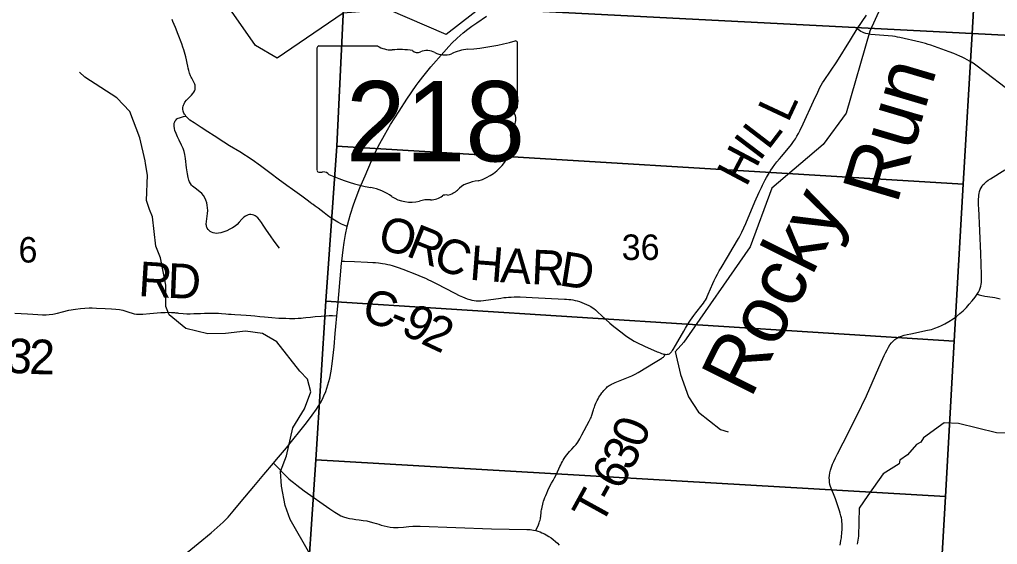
# Model space of a CAD drawing. Extents: x 0 to 34, y 0 to 22.
# Drawn here: x 26.889 to 28.495, y 15.04 to 15.902 of the extents above; entities that cross this region are included whole.
import ezdxf

# ---------------------------------------------------------------- set-up
doc = ezdxf.new("R2010")
doc.units = 0
for name, color, linetype in [('GM_X_County_Road', 7, 'Continuous'), ('GM_X_County_Road_Text', 7, 'Continuous'), ('GM_X_Minor_River', 7, 'Continuous'), ('GM_X_Minor_River_Text', 7, 'Continuous'), ('GM_X_Section', 7, 'Continuous'), ('GM_X_Section_Text', 7, 'Continuous'), ('GM_X_State_Location', 7, 'Continuous'), ('GM_X_State_Route', 7, 'Continuous'), ('GM_X_State_Shield', 7, 'Continuous'), ('GM_X_Township_Road', 7, 'Continuous'), ('GM_X_Township_Road_Text', 7, 'Continuous')]:
    doc.layers.add(name, color=color, linetype=linetype)

msp = doc.modelspace()

# ---------------------------------------------------------------- linework, layer by layer
at = {"layer": 'GM_X_County_Road'}
for points in [[(27.376, 15.5941), (27.3744, 15.5953), (27.3711, 15.5978), (27.3692, 15.5992), (27.3663, 15.6014), (27.3614, 15.6052), (27.3526, 15.6117), (27.3449, 15.6173), (27.3374, 15.6228), (27.3281, 15.6294), (27.3139, 15.6396), (27.3022, 15.6483), (27.2846, 15.6614), (27.2709, 15.6714), (27.2506, 15.6845), (27.2339, 15.6941), (27.2244, 15.7003), (27.2084, 15.7105), (27.1981, 15.7174), (27.187, 15.7245), (27.1757, 15.732), (27.1688, 15.7366), (27.1645, 15.7403), (27.1631, 15.7418), (27.1619, 15.7431), (27.1607, 15.7449), (27.1597, 15.7464), (27.1589, 15.748), (27.1576, 15.7514), (27.1571, 15.7543), (27.1572, 15.7573), (27.1576, 15.7595), (27.1581, 15.7611), (27.159, 15.7632), (27.1605, 15.7658), (27.1632, 15.7691), (27.1649, 15.7708), (27.1713, 15.7773), (27.1735, 15.78), (27.1753, 15.7826), (27.1766, 15.7849), (27.1769, 15.7857), (27.1771, 15.7867), (27.1775, 15.7884), (27.1775, 15.7912), (27.1772, 15.7937), (27.1767, 15.7953), (27.1756, 15.7977), (27.1735, 15.8021), (27.1718, 15.8055), (27.171, 15.8071), (27.1698, 15.8093), (27.168, 15.8138), (27.1675, 15.8155), (27.1669, 15.8179), (27.166, 15.8215), (27.1652, 15.825), (27.1642, 15.8298), (27.1633, 15.8353), (27.162, 15.8405), (27.1588, 15.8517), (27.1572, 15.8564), (27.1554, 15.8615), (27.1496, 15.8772), (27.1449, 15.8887), (27.1408, 15.8984), (27.1393, 15.9015)], [(28.2648, 15.8862), (28.2802, 15.9088)], [(27.4183, 15.505), (27.4226, 15.5049), (27.439, 15.5044), (27.4603, 15.5035), (27.469, 15.503), (27.4738, 15.5027), (27.4785, 15.5021), (27.4818, 15.5017), (27.4853, 15.5012), (27.4894, 15.5005), (27.4938, 15.4997), (27.4973, 15.4988), (27.5011, 15.4978), (27.5056, 15.4963), (27.511, 15.4945), (27.5185, 15.4918), (27.5406, 15.4832), (27.5488, 15.4798), (27.5554, 15.4769), (27.5605, 15.4745), (27.5646, 15.4725), (27.5689, 15.4704), (27.5731, 15.4683), (27.6038, 15.4524), (27.611, 15.4486), (27.6164, 15.4462), (27.6205, 15.4445), (27.6242, 15.4432), (27.6287, 15.4419), (27.632, 15.441), (27.6355, 15.4404), (27.639, 15.44), (27.6429, 15.4398), (27.6468, 15.44), (27.6511, 15.4403), (27.6793, 15.4444), (27.6843, 15.4451), (27.6881, 15.4455), (27.6919, 15.4459), (27.6965, 15.4461), (27.7012, 15.4463), (27.706, 15.4463), (27.7113, 15.4463), (27.7308, 15.4455), (27.7838, 15.4426), (27.7875, 15.4425), (27.7909, 15.4422), (27.7943, 15.4419), (27.7978, 15.4413), (27.8013, 15.4406), (27.8048, 15.4398), (27.8085, 15.4386), (27.8125, 15.4372), (27.8162, 15.4357), (27.8202, 15.434), (27.8237, 15.4324), (27.827, 15.4306), (27.8295, 15.429), (27.8321, 15.4271), (27.835, 15.4249), (27.8381, 15.422), (27.8451, 15.4152), (27.8584, 15.4034), (27.8651, 15.3977), (27.8785, 15.3872), (27.882, 15.3847), (27.8865, 15.3814), (27.8986, 15.3738), (27.9026, 15.3717), (27.9074, 15.3693), (27.9112, 15.3674), (27.9151, 15.3656), (27.9362, 15.3564), (27.9386, 15.3554), (27.941, 15.3544), (27.9433, 15.3536), (27.9456, 15.3529), (27.9467, 15.3525), (27.9476, 15.3523), (27.9485, 15.3522), (27.9495, 15.3521), (27.9514, 15.352), (27.9533, 15.3521), (27.9548, 15.3525), (27.9564, 15.353), (27.9576, 15.3539), (27.9586, 15.3548), (27.9596, 15.3559), (27.9605, 15.3571), (27.9615, 15.3584), (27.9625, 15.36), (27.9701, 15.3732), (27.9797, 15.39), (27.9827, 15.395), (27.9858, 15.4002), (27.9887, 15.4046), (27.9911, 15.408), (27.9937, 15.4117), (27.9965, 15.4156), (27.9997, 15.4199), (28.0101, 15.4331), (28.0123, 15.4361), (28.014, 15.4385), (28.0155, 15.441), (28.0171, 15.4439), (28.0185, 15.4469), (28.0202, 15.4506), (28.0278, 15.4682), (28.03, 15.4731), (28.0327, 15.4786), (28.0352, 15.4834), (28.0382, 15.4891), (28.0411, 15.494), (28.0516, 15.5116), (28.0611, 15.5272), (28.0698, 15.5422), (28.0717, 15.5458), (28.0736, 15.5495), (28.075, 15.5524), (28.0816, 15.567), (28.0967, 15.6023), (28.1038, 15.618), (28.1073, 15.6256), (28.1093, 15.6299), (28.1115, 15.6342), (28.1136, 15.6382), (28.116, 15.6424), (28.1207, 15.6503), (28.123, 15.6541), (28.1255, 15.6581), (28.1293, 15.6635), (28.1327, 15.6678), (28.137, 15.673), (28.1409, 15.6774), (28.1566, 15.6963), (28.1603, 15.7011), (28.1633, 15.7056), (28.1658, 15.7099), (28.1682, 15.7143), (28.1711, 15.7201), (28.1762, 15.7305), (28.193, 15.7674), (28.2, 15.7826), (28.2018, 15.7864), (28.2036, 15.7898), (28.2057, 15.7937), (28.2078, 15.7974), (28.2105, 15.8016), (28.2311, 15.8321), (28.2537, 15.8685), (28.2648, 15.8862)], [(28.5076, 15.7901), (28.4779, 15.8128), (28.4573, 15.8282), (28.4534, 15.8308), (28.4491, 15.8335), (28.4453, 15.8356), (28.4417, 15.8374), (28.4372, 15.8397), (28.4332, 15.8416), (28.4283, 15.8438), (28.4234, 15.8459), (28.4156, 15.8488), (28.3858, 15.8593), (28.3815, 15.8608), (28.3771, 15.8621), (28.3726, 15.8634), (28.3682, 15.8645), (28.3346, 15.8722), (28.3309, 15.8728), (28.3269, 15.8735), (28.3227, 15.874), (28.2869, 15.8772), (28.2823, 15.8779), (28.2789, 15.8786), (28.2757, 15.8796), (28.2732, 15.8807), (28.2709, 15.8819), (28.2684, 15.8834), (28.2648, 15.8862)], [(28.3323, 15.38), (28.3331, 15.3805), (28.3372, 15.3821), (28.3416, 15.3834), (28.3468, 15.3846), (28.3527, 15.3859), (28.3804, 15.3915), (28.3865, 15.393), (28.3923, 15.3948), (28.398, 15.3969), (28.4032, 15.3993), (28.4089, 15.4022), (28.4152, 15.4059), (28.4226, 15.4104), (28.4279, 15.4143), (28.4334, 15.4188), (28.4386, 15.4234), (28.4442, 15.4291), (28.4488, 15.4342), (28.4536, 15.4397), (28.4582, 15.4457), (28.4618, 15.451), (28.4637, 15.454), (28.4654, 15.4573), (28.4668, 15.4608), (28.4678, 15.464), (28.4684, 15.4671), (28.4688, 15.47), (28.4691, 15.4734), (28.4691, 15.4768), (28.469, 15.4823), (28.4676, 15.5174), (28.4643, 15.5922), (28.4641, 15.5961), (28.464, 15.6003), (28.464, 15.6035), (28.4641, 15.6066), (28.4643, 15.6104), (28.4645, 15.6132), (28.465, 15.6162), (28.4658, 15.6193), (28.4668, 15.6224), (28.4683, 15.6255), (28.4697, 15.6278), (28.4713, 15.63), (28.473, 15.6318), (28.4747, 15.6335), (28.4771, 15.6356), (28.48, 15.6378), (28.4834, 15.64), (28.5073, 15.6547)], [(27.427, 15.5618), (27.423, 15.5633), (27.4178, 15.5656), (27.4119, 15.5687), (27.4009, 15.5757), (27.3948, 15.5799), (27.3892, 15.5842), (27.3842, 15.5881), (27.3792, 15.5918), (27.376, 15.5941)], [(28.2365, 15.039), (28.2373, 15.0427), (28.238, 15.0467), (28.2387, 15.0508), (28.2391, 15.0544), (28.2395, 15.0574), (28.2397, 15.0608), (28.2399, 15.0637), (28.2399, 15.0742), (28.2397, 15.0773), (28.2393, 15.0806), (28.2389, 15.0834), (28.2381, 15.0867), (28.237, 15.0911), (28.2359, 15.0949), (28.2289, 15.1148), (28.221, 15.135), (28.22, 15.1386), (28.2194, 15.142), (28.219, 15.1455), (28.2188, 15.1491), (28.2191, 15.1531), (28.2198, 15.1574), (28.2208, 15.1619), (28.2225, 15.167), (28.2244, 15.1716), (28.2263, 15.1762), (28.2291, 15.182), (28.2323, 15.1887), (28.2415, 15.2069), (28.2643, 15.2511), (28.28, 15.2838), (28.3043, 15.3393), (28.3069, 15.345), (28.3092, 15.3499), (28.3113, 15.3545), (28.3138, 15.3595), (28.3161, 15.3637), (28.3185, 15.3676), (28.321, 15.3707), (28.3239, 15.3739), (28.3267, 15.3765), (28.3298, 15.3787), (28.3323, 15.38)], [(27.306, 15.1733), (27.3081, 15.1711), (27.3256, 15.1532), (27.3292, 15.1498), (27.3314, 15.1478), (27.3347, 15.1451), (27.339, 15.1416), (27.3445, 15.1372), (27.3566, 15.1281), (27.3986, 15.0982), (27.4069, 15.0928), (27.4121, 15.0896), (27.4166, 15.0871), (27.4211, 15.0853), (27.4262, 15.0837), (27.4311, 15.0825), (27.4357, 15.0818), (27.441, 15.081), (27.4468, 15.0804), (27.4533, 15.0795), (27.4591, 15.0785), (27.4648, 15.0773), (27.4709, 15.0757), (27.4751, 15.0744), (27.4789, 15.0731), (27.4829, 15.0719), (27.4878, 15.0705), (27.4928, 15.0692), (27.4978, 15.0684), (27.5032, 15.0678), (27.5109, 15.0678), (27.5195, 15.0684), (27.5281, 15.0692), (27.5349, 15.0698), (27.5407, 15.0699), (27.5467, 15.0698), (27.664, 15.0656), (27.7223, 15.0645), (27.7274, 15.0643), (27.7305, 15.064), (27.7332, 15.0635), (27.737, 15.0627), (27.7403, 15.0617), (27.7438, 15.0606), (27.7469, 15.0592), (27.7509, 15.0573), (27.7541, 15.0555), (27.7582, 15.0532), (27.7618, 15.0508), (27.7656, 15.0479), (27.7692, 15.0451), (27.7725, 15.042), (27.7754, 15.0386)]]:
    msp.add_lwpolyline(points, dxfattribs=at)
at = {"layer": 'GM_X_Minor_River'}
for points in [[(28.4678, 16.383), (28.4473, 16.2989), (28.4687, 16.2373), (28.4626, 16.2034), (28.4068, 16.1494), (28.3695, 16.0675), (28.2854, 15.8822), (28.2465, 15.7479), (28.2089, 15.6967), (28.1244, 15.6246), (28.0888, 15.5286), (27.98, 15.372), (27.9658, 15.356)], [(27.8486, 15.9861), (27.7758, 15.951), (27.6723, 15.9417), (27.5896, 15.8768), (27.4942, 15.9181), (27.4206, 15.9121), (27.3119, 15.8379), (27.2763, 15.8588), (27.2368, 15.9154)], [(27.3116, 15.3727), (27.2881, 15.386), (27.26, 15.3902), (27.2271, 15.3863), (27.1982, 15.3856), (27.1619, 15.3946), (27.1349, 15.4171), (27.1289, 15.4304), (27.1289, 15.4657), (27.1202, 15.5106), (27.1126, 15.5296), (27.107, 15.5779), (27.1024, 15.5896), (27.0975, 15.6045), (27.099, 15.6463), (27.0956, 15.6653), (27.0952, 15.6695), (27.0862, 15.7075), (27.0702, 15.7508), (27.0486, 15.7732), (26.9963, 15.807), (26.9873, 15.8154)], [(27.4801, 14.9479), (27.4347, 15.0056), (27.406, 15.0186), (27.3843, 15.0231), (27.3658, 15.0245), (27.3335, 15.081), (27.3251, 15.104), (27.3189, 15.1354), (27.3177, 15.1597), (27.3275, 15.1852), (27.338, 15.2316), (27.3571, 15.2625), (27.3674, 15.2906), (27.3616, 15.3113), (27.3495, 15.3246), (27.3115, 15.3728)], [(27.9655, 15.3569), (27.9744, 15.3187), (27.9874, 15.2821), (28.004, 15.2569), (28.0402, 15.2289), (28.0527, 15.225)], [(28.5405, 15.2213), (28.4933, 15.2231), (28.431, 15.2384), (28.4076, 15.2396), (28.3736, 15.2148), (28.3693, 15.2081), (28.3619, 15.2038), (28.3474, 15.1872), (28.3347, 15.1785), (28.3334, 15.1724), (28.3072, 15.1558), (28.2823, 15.1201), (28.2677, 15.0993), (28.267, 15.0538), (28.2644, 15.0406)]]:
    msp.add_lwpolyline(points, dxfattribs=at)
at = {"layer": 'GM_X_Section'}
for points in [[(27.7176, 16.0274), (28.4594, 15.9845), (28.4533, 15.8787), (27.7054, 15.9168)], [(26.3734, 15.9843), (27.4216, 15.9328), (27.4099, 15.6936), (27.392, 15.4391), (27.3753, 15.1787), (27.3574, 14.9107), (27.3572, 14.9074), (26.2944, 14.9601)], [(28.4594, 15.9845), (29.1085, 15.9479), (29.1198, 15.9322), (29.1285, 15.9182), (29.151, 15.885), (29.1594, 15.8732), (29.1693, 15.86), (29.1769, 15.8494), (29.1887, 15.8408), (28.6965, 15.8662), (28.4533, 15.8787)], [(27.4216, 15.9328), (27.7054, 15.9168), (28.4533, 15.8787), (28.439, 15.6312), (27.4099, 15.6936)], [(28.4533, 15.8787), (28.6965, 15.8662), (28.6747, 15.5464), (28.6572, 15.29), (28.6412, 15.0549), (28.6267, 14.8415), (28.3943, 14.8549), (28.4095, 15.1186), (28.4242, 15.3738), (28.439, 15.6312)], [(28.439, 15.6312), (28.4242, 15.3738), (27.392, 15.4391), (27.4099, 15.6936)], [(27.392, 15.4391), (28.4242, 15.3738), (28.4095, 15.1186), (27.3753, 15.1787)], [(28.4095, 15.1186), (28.3943, 14.8549), (27.3574, 14.9107), (27.3753, 15.1787)]]:
    msp.add_lwpolyline(points, close=True, dxfattribs=at)
at = {"layer": 'GM_X_State_Route'}
msp.add_lwpolyline([(27.1584, 15.0216), (27.1824, 15.0415), (27.2035, 15.0591), (27.2234, 15.0768), (27.2313, 15.085), (27.2398, 15.0947), (27.2531, 15.1105), (27.2739, 15.1353), (27.2902, 15.1548), (27.306, 15.1733), (27.3111, 15.1794), (27.3274, 15.1988), (27.3379, 15.2118), (27.3495, 15.2261), (27.36, 15.2394), (27.3696, 15.2521), (27.3766, 15.2621), (27.3834, 15.2726), (27.3864, 15.2785), (27.3886, 15.2837), (27.3917, 15.2913), (27.3954, 15.3021), (27.3985, 15.3128), (27.4008, 15.3245), (27.4025, 15.3365), (27.4054, 15.3641), (27.4073, 15.386), (27.4084, 15.3975), (27.4099, 15.4155), (27.4114, 15.4312), (27.4131, 15.4503), (27.4155, 15.4758), (27.4179, 15.5015), (27.4183, 15.505), (27.4203, 15.5235), (27.422, 15.5358), (27.4242, 15.5489), (27.427, 15.5618), (27.4296, 15.5722), (27.4323, 15.5822), (27.4373, 15.5975), (27.4416, 15.6095), (27.448, 15.6254), (27.4563, 15.645), (27.4671, 15.6699), (27.4736, 15.6844), (27.4804, 15.6981), (27.4881, 15.7119), (27.4981, 15.7291), (27.5126, 15.7514), (27.525, 15.7706), (27.5403, 15.7932), (27.5436, 15.7978), (27.5512, 15.8077), (27.5646, 15.8237), (27.5855, 15.8479), (27.594, 15.8573), (27.5991, 15.8627), (27.6075, 15.8708), (27.6177, 15.8796), (27.6252, 15.8857), (27.6316, 15.8906), (27.64, 15.8964), (27.6558, 15.9073)], dxfattribs=at)
at = {"layer": 'GM_X_State_Shield'}
for p, q in [((27.3774, 15.8547), (27.3774, 15.6546)), ((27.4772, 15.8581), (27.3807, 15.8581)), ((27.707, 15.7584), (27.707, 15.8631)), ((27.707, 15.7584), (27.707, 15.7584))]:
    msp.add_line(p, q, dxfattribs=at)
for centre, major_axis, start_param, end_param in [((27.3812, 15.8551), (0.00382, 0), 1.712693, 3.28349), ((27.5002, 15.8813), (0.037, 0), 4.042523, 4.731795), ((27.6342, 15.797), (0.0703, 0), 1.699011, 2.107814), ((27.5896, 16.1309), (0.3495, 0), 4.814394, 5.042369), ((27.7033, 15.8635), (0.00367, 0), 6.141152, 7.989035), ((27.5124, 15.7458), (0.133, 0), 1.404758, 1.657858), ((27.5426, 15.8561), (0.0107, 0), 3.836095, 5.185415), ((27.5583, 15.833), (0.0222, 0), 0.950623, 2.079405), ((27.587, 15.8647), (0.0267, 0), 4.081561, 5.145723), ((27.7031, 15.758), (0.00393, 0), 5.05454, 6.418171), ((27.7061, 15.7507), (0.00568, 0), 1.883978, 3.671073), ((27.67, 15.7375), (0.0341, 0), 5.934695, 6.695948), ((27.7201, 15.7146), (0.0248, 0), 2.387724, 3.262537), ((27.6092, 15.7013), (0.0874, 0), 5.101752, 6.440018), ((27.3812, 15.6541), (0.00385, 0), 3.00124, 4.508301), ((27.3818, 15.6746), (0.0294, 0), 4.665946, 4.897461), ((27.3878, 15.643), (0.0106, 0), 0.519207, 1.627899), ((27.5216, 15.8228), (0.2524, 0), 4.195997, 4.488961), ((27.646, 15.5984), (0.0479, 0), 1.647645, 2.488434), ((27.4464, 15.5646), (0.079, 0), 0.823519, 1.323587), ((27.5644, 15.627), (0.0267, 0), 4.691044, 5.507374), ((27.5886, 15.6076), (0.00752, 0), 1.147584, 2.315152), ((27.5854, 15.6352), (0.0282, 0), 4.937069, 5.64225), ((27.5318, 15.642), (0.0501, 0), 4.026481, 4.996735), ((27.5608, 15.5728), (0.0412, 0), 1.495662, 1.94098)]:
    msp.add_ellipse(centre, major_axis=major_axis, ratio=0.8, start_param=start_param, end_param=end_param, dxfattribs=at)
at = {"layer": 'GM_X_Township_Road'}
for points in [[(27.3159, 15.5265), (27.3071, 15.5377), (27.3009, 15.5464), (27.2943, 15.556), (27.2892, 15.5638), (27.2862, 15.5685), (27.2829, 15.5729), (27.28, 15.5763), (27.2778, 15.5783), (27.2758, 15.5796), (27.2739, 15.5804), (27.2713, 15.581), (27.2686, 15.5814), (27.2667, 15.5814), (27.2643, 15.5809), (27.262, 15.58), (27.2598, 15.5788), (27.2573, 15.577), (27.2541, 15.574), (27.2496, 15.569), (27.2462, 15.5653), (27.2429, 15.5625), (27.2388, 15.5597), (27.2345, 15.5573), (27.2294, 15.5549), (27.2242, 15.5529), (27.2194, 15.5515), (27.2158, 15.5508), (27.2127, 15.5506), (27.2096, 15.5508), (27.2071, 15.5513), (27.2042, 15.5523), (27.2021, 15.5536), (27.2002, 15.5552), (27.1986, 15.5571), (27.1973, 15.5592), (27.1967, 15.5605), (27.1962, 15.5617), (27.1958, 15.5636), (27.1956, 15.565), (27.1956, 15.5668), (27.1957, 15.5687), (27.1959, 15.5701), (27.1964, 15.5744), (27.1975, 15.5833), (27.1979, 15.588), (27.1978, 15.5923), (27.1973, 15.5966), (27.1964, 15.6008), (27.195, 15.605), (27.1932, 15.6089), (27.1908, 15.6126), (27.1881, 15.6159), (27.185, 15.6189), (27.1771, 15.625), (27.1732, 15.6281), (27.1715, 15.6299), (27.1697, 15.6324), (27.1682, 15.6351), (27.167, 15.638), (27.1658, 15.6422), (27.1646, 15.6483), (27.1633, 15.6581), (27.1614, 15.6735), (27.1603, 15.6803), (27.1591, 15.6851), (27.1575, 15.6898), (27.155, 15.6954), (27.1509, 15.7037), (27.1481, 15.7092), (27.1459, 15.7143), (27.1442, 15.7196), (27.1433, 15.7226), (27.1428, 15.7263), (27.1428, 15.7294), (27.143, 15.7312), (27.1438, 15.7335), (27.1446, 15.7352), (27.146, 15.7372), (27.1474, 15.7385), (27.1495, 15.7396), (27.1516, 15.7404), (27.1547, 15.7413), (27.1582, 15.7422), (27.1619, 15.7431)], [(28.4618, 15.451), (28.465, 15.4496), (28.4671, 15.449), (28.4694, 15.4484), (28.4719, 15.4479), (28.4745, 15.4475), (28.4867, 15.4458), (28.4909, 15.4452), (28.495, 15.4444), (28.4993, 15.4434)], [(26.8809, 15.4194), (26.9017, 15.4187), (26.9109, 15.4181), (26.9191, 15.4175), (26.9267, 15.4168), (26.9326, 15.4168), (26.9377, 15.4172), (26.9436, 15.4182), (26.951, 15.4198), (26.9592, 15.422), (26.9696, 15.4243), (26.9809, 15.4262), (26.9888, 15.4274), (26.9961, 15.428), (27.0035, 15.4283), (27.0084, 15.4281), (27.0152, 15.428), (27.0293, 15.4273), (27.04, 15.4268), (27.0468, 15.4264), (27.053, 15.4256), (27.0584, 15.4245), (27.0632, 15.4231), (27.0684, 15.4212), (27.0736, 15.4194), (27.0772, 15.4186), (27.0808, 15.418), (27.0855, 15.4177), (27.0915, 15.4179), (27.1028, 15.419), (27.1208, 15.4206), (27.1281, 15.4209), (27.1324, 15.421), (27.1385, 15.4208), (27.1434, 15.4205), (27.1453, 15.4203), (27.1484, 15.4199), (27.1502, 15.4198), (27.1576, 15.4189), (27.1637, 15.4184), (27.1662, 15.4184), (27.1693, 15.4184), (27.1754, 15.4188), (27.186, 15.4192), (27.1926, 15.4194), (27.2023, 15.4194), (27.21, 15.4194), (27.2154, 15.4194), (27.2205, 15.4192), (27.2277, 15.4186), (27.232, 15.4182), (27.2363, 15.4179), (27.2425, 15.4175), (27.2524, 15.4168), (27.261, 15.4162), (27.2688, 15.4157), (27.2756, 15.4151), (27.2837, 15.4143), (27.2911, 15.4135), (27.3034, 15.4123), (27.3145, 15.4116), (27.3263, 15.4112), (27.3325, 15.4111), (27.3411, 15.411), (27.3467, 15.4112), (27.3515, 15.4116), (27.3549, 15.412), (27.3591, 15.4124), (27.3665, 15.4131), (27.3708, 15.4135), (27.3744, 15.4139), (27.3843, 15.4148), (27.3924, 15.4153), (27.3975, 15.4156), (27.4027, 15.4157), (27.4099, 15.4155)], [(27.737, 15.0627), (27.7411, 15.0724), (27.7423, 15.0753), (27.7431, 15.0776), (27.7438, 15.0799), (27.7443, 15.0819), (27.7446, 15.084), (27.7449, 15.0859), (27.7457, 15.0929), (27.7459, 15.0947), (27.7462, 15.0966), (27.7466, 15.0986), (27.749, 15.1086), (27.7497, 15.1112), (27.7505, 15.1137), (27.7518, 15.1173), (27.7531, 15.1205), (27.7548, 15.1244), (27.7565, 15.1283), (27.7594, 15.1344), (27.7626, 15.1404), (27.7651, 15.1449), (27.7675, 15.1495), (27.77, 15.1542), (27.7725, 15.1593), (27.7748, 15.1643), (27.7764, 15.1678), (27.7778, 15.1708), (27.7792, 15.1734), (27.7805, 15.176), (27.7819, 15.1785), (27.7836, 15.1813), (27.7856, 15.1843), (27.788, 15.1873), (27.7924, 15.1925), (27.7961, 15.1965), (27.8, 15.2005), (27.803, 15.2042), (27.8056, 15.2078), (27.8089, 15.2133), (27.8125, 15.2198), (27.8247, 15.2421), (27.8258, 15.2445), (27.8268, 15.2466), (27.8276, 15.2486), (27.8284, 15.2508), (27.8316, 15.2612), (27.8322, 15.263), (27.833, 15.2652), (27.8337, 15.2673), (27.8346, 15.2694), (27.8356, 15.2718), (27.8366, 15.2739), (27.8378, 15.2763), (27.8393, 15.2792), (27.8406, 15.2815), (27.842, 15.2839), (27.8436, 15.2863), (27.8453, 15.2886), (27.847, 15.2907), (27.8485, 15.2925), (27.8505, 15.2948), (27.8529, 15.2972), (27.8542, 15.2986), (27.8558, 15.2998), (27.8575, 15.3009), (27.8594, 15.3021), (27.8614, 15.3032), (27.8639, 15.3044), (27.867, 15.3056), (27.8948, 15.3169), (27.8977, 15.3182), (27.9003, 15.3196), (27.9047, 15.3222), (27.9329, 15.3393), (27.9436, 15.3457), (27.9451, 15.3466), (27.9464, 15.3476), (27.9473, 15.3486), (27.9481, 15.3497), (27.9495, 15.3521)]]:
    msp.add_lwpolyline(points, dxfattribs=at)

# ---------------------------------------------------------------- texts
at = {"layer": 'GM_X_County_Road_Text'}
for s, rotation, p in [('L', 64.9447, (28.1511, 15.7309)), ('L', 52.5751, (28.1185, 15.6859)), ('I', 52.8936, (28.1044, 15.6674)), ('H', 62.0916, (28.0823, 15.6252)), ('O', 346.1466, (27.4752, 15.5256)), ('R', 338.1479, (27.5217, 15.5143)), ('C', 337.5053, (27.5649, 15.4969)), ('H', 355.5342, (27.6269, 15.4746)), ('A', 356.3425, (27.6776, 15.4706)), ('R', 357.5012, (27.7288, 15.4673)), ('D', 351.0036, (27.7737, 15.4655)), ('C', 346.7769, (27.4493, 15.4058)), ('9', 332.8252, (27.5129, 15.3877)), ('-', 337.9181, (27.4925, 15.3959)), ('2', 334.851, (27.546, 15.3707))]:
    msp.add_text(s, height=0.0568, rotation=rotation, dxfattribs=at).set_placement(p)
at = {"layer": 'GM_X_Minor_River_Text'}
for s, rotation, p in [('Run', 73.5135, (28.3299, 15.5966)), ('Rocky', 63.5135, (28.0899, 15.2777))]:
    msp.add_text(s, height=0.0947, rotation=rotation, dxfattribs=at).set_placement(p)
at = {"layer": 'GM_X_Section_Text'}
for s, height, p in [('36', 0.04186, (27.8779, 15.5069)), ('6', 0.0419, (26.8871, 15.5027))]:
    msp.add_text(s, height=height, rotation=0, dxfattribs=at).set_placement(p)
at = {"layer": 'GM_X_State_Location'}
for s in ['s', 'r']:
    msp.add_text(s, height=0.000189, dxfattribs=at).set_placement((27.5385, 15.7413))
msp.add_text('218', height=0.000189, rotation=0, dxfattribs=at).set_placement((27.4716, 15.7275))
at = {"layer": 'GM_X_State_Shield'}
msp.add_text('218', height=0.13184, dxfattribs=at).set_placement((27.425, 15.6687))
at = {"layer": 'GM_X_Township_Road_Text'}
for s, rotation, p in [('R', 356.4285, (27.0831, 15.4479)), ('D', 357.7398, (27.1311, 15.4449)), ('3', 355.2612, (26.8655, 15.3228)), ('2', 358.8557, (26.9043, 15.3198)), ('0', 68.8146, (27.9119, 15.1958)), ('3', 62.6549, (27.8931, 15.1587)), ('6', 61.4427, (27.8757, 15.1268)), ('T', 61.1593, (27.8439, 15.0688)), ('-', 61.2133, (27.8644, 15.1061))]:
    msp.add_text(s, height=0.0568, rotation=rotation, dxfattribs=at).set_placement(p)

doc.saveas('drawing.dxf')
